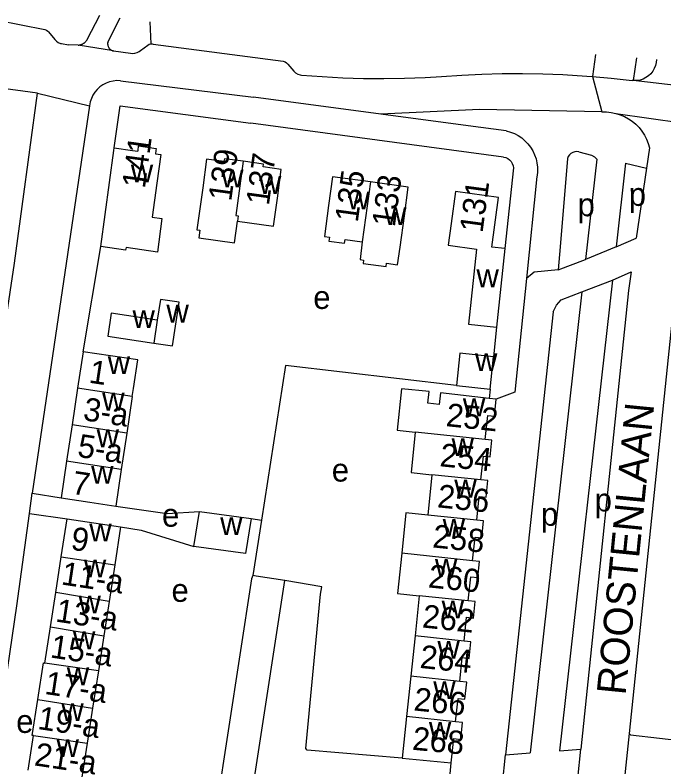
# Model space of a CAD drawing. Extents: x 161093 to 163177, y 379000 to 380904.
# Drawn here: x 162136.9 to 162248.8, y 380643.6 to 380773.4 of the extents above; entities that cross this region are included whole.
import ezdxf

# ---------------------------------------------------------------- set-up
doc = ezdxf.new("R2010")
doc.units = 0
for name, color, linetype in [('BLT_Basislijn', 7, 'Continuous'), ('BLT_Bebouwing', 7, 'Continuous'), ('BLT_Centroide', 7, 'Continuous'), ('BLT_Huisnummer', 7, 'Continuous'), ('BLT_Huisnummer_ tussenligend', 7, 'Continuous'), ('BLT_Huisnummer_reeks', 7, 'Continuous'), ('BLT_Onderverdeling_panden', 7, 'Continuous'), ('BLT_Straatnaam', 7, 'Continuous'), ('BLT_Vlakafsluiter', 7, 'Continuous')]:
    doc.layers.add(name, color=color, linetype=linetype)

msp = doc.modelspace()

# ---------------------------------------------------------------- linework, layer by layer
at = {"layer": 'BLT_Basislijn'}
for p, q in [((162130.53, 380773.08), (162142.01, 380770.9)), ((162149.32, 380769.16), (162151.51, 380773.37)), ((162152.85, 380768.67), (162154.99, 380772.89)), ((162160.13, 380772.18), (162160.28, 380768.4)), ((162142.62, 380770.47), (162143.7, 380769.17)), ((162144.85, 380768.43), (162146.08, 380768.25)), ((162147.74, 380768.18), (162146.08, 380768.25)), ((162153.82, 380767.17), (162147.74, 380768.18)), ((162158.49, 380767.27), (162159.79, 380768.19)), ((162160.71, 380768.33), (162183.14, 380765.38)), ((162153.82, 380767.17), (162156.78, 380766.8)), ((162237, 380766.53), (162236.48, 380762.74)), ((162244.12, 380765.98), (162243.54, 380762.07)), ((162247.55, 380765.72), (162247.48, 380765.16)), ((162183.92, 380764.89), (162184.95, 380763.68)), ((162155.04, 380762.03), (162178.01, 380759.21)), ((162243.54, 380762.07), (162243.36, 380762.08)), ((162200, 380756.26), (162178.01, 380759.21)), ((162149.68, 380757.7), (162139.81, 380690.86)), ((162215.06, 380754.25), (162200, 380756.26)), ((162221.13, 380748.86), (162177.52, 380754.69)), ((162221.62, 380753.37), (162215.06, 380754.25)), ((162232.19, 380748.6), (162230.93, 380733.36)), ((162222.85, 380747), (162221.35, 380733.05)), ((162242.19, 380747.81), (162245.81, 380746.93)), ((162148.61, 380715.26), (162151.65, 380733.4)), ((162230.93, 380733.36), (162230.6, 380729.38)), ((162240.57, 380733.34), (162235.29, 380731.15)), ((162234.66, 380725.57), (162239.93, 380727.62)), ((162229.74, 380722.16), (162221.47, 380645.69)), ((162219.91, 380719.49), (162219.43, 380714.38)), ((162218.85, 380708.82), (162218.7, 380707.18)), ((162139.32, 380687.33), (162139.81, 380690.86)), ((162139.81, 380690.86), (162144.79, 380690.03)), ((162139.32, 380687.33), (162145.83, 380686.43)), ((162177.6, 380686.44), (162179.36, 380686.16)), ((162179.36, 380686.16), (162177.86, 380676.61)), ((162220.95, 380640.64), (162221.47, 380645.69)), ((162221.47, 380645.69), (162225.75, 380646)), ((162230.82, 380646.36), (162234.52, 380646.63)), ((162233.98, 380641.58), (162234.52, 380646.63)), ((162211.69, 380639.44), (162212.13, 380644.29))]:
    msp.add_line(p, q, dxfattribs=at)
for points in [[(162140.7, 380759.86), (162051.87, 380771.94)], [(162142.01, 380770.9), (162142.29, 380770.78), (162142.52, 380770.6), (162142.62, 380770.47)], [(162143.7, 380769.17), (162143.98, 380768.87), (162144.32, 380768.64), (162144.69, 380768.48), (162144.85, 380768.43)], [(162147.74, 380768.18), (162147.82, 380768.18), (162147.91, 380768.19), (162147.99, 380768.21), (162148.07, 380768.22), (162148.15, 380768.25), (162148.23, 380768.27), (162148.31, 380768.3), (162148.39, 380768.33), (162148.47, 380768.37), (162148.54, 380768.41), (162148.62, 380768.45), (162148.69, 380768.49), (162148.76, 380768.54), (162148.83, 380768.59), (162148.89, 380768.65), (162148.96, 380768.71), (162149.02, 380768.77), (162149.08, 380768.83), (162149.13, 380768.89), (162149.18, 380768.96), (162149.23, 380769.02), (162149.27, 380769.09), (162149.32, 380769.16)], [(162152.85, 380768.67), (162152.84, 380768.59), (162152.83, 380768.51), (162152.83, 380768.43), (162152.83, 380768.35), (162152.84, 380768.26), (162152.85, 380768.18), (162152.87, 380768.1), (162152.9, 380768.01), (162152.93, 380767.93), (162152.97, 380767.85), (162153.01, 380767.77), (162153.06, 380767.69), (162153.12, 380767.62), (162153.17, 380767.55), (162153.24, 380767.49), (162153.3, 380767.43), (162153.37, 380767.38), (162153.44, 380767.33), (162153.52, 380767.29), (162153.59, 380767.25), (162153.67, 380767.22), (162153.74, 380767.19), (162153.82, 380767.17)], [(162159.79, 380768.19), (162160.02, 380768.33), (162160.28, 380768.4), (162160.54, 380768.38), (162160.71, 380768.33)], [(162156.78, 380766.8), (162157.16, 380766.75), (162157.55, 380766.78), (162157.92, 380766.89), (162158.26, 380767.08), (162158.49, 380767.27)], [(162183.14, 380765.38), (162183.44, 380765.28), (162183.71, 380765.11), (162183.92, 380764.89)], [(162247.48, 380765.16), (162247.36, 380764.64), (162247.16, 380764.13), (162246.89, 380763.66), (162246.55, 380763.24), (162246.15, 380762.87), (162245.71, 380762.56), (162245.22, 380762.32), (162244.71, 380762.15), (162244.17, 380762.07), (162243.54, 380762.07)], [(162184.95, 380763.68), (162185.27, 380763.4), (162185.65, 380763.19), (162186.05, 380763.06), (162186.31, 380763.01)], [(162186.31, 380763.01), (162189.85, 380762.74), (162193.4, 380762.55), (162196.96, 380762.43), (162200.51, 380762.4), (162204.07, 380762.45), (162207.62, 380762.58), (162210.45, 380762.74)], [(162210.45, 380762.74), (162213.93, 380763), (162217.42, 380763.18), (162220.92, 380763.28), (162224.41, 380763.3), (162227.91, 380763.24), (162231.37, 380763.11)], [(162231.37, 380763.11), (162235.55, 380762.83), (162236.48, 380762.74)], [(162236.48, 380762.74), (162239.72, 380762.46), (162243.36, 380762.08)], [(162155.04, 380762.03), (162154.41, 380762.05), (162153.78, 380761.98), (162153.17, 380761.84), (162152.58, 380761.62), (162152.02, 380761.32), (162151.51, 380760.96), (162151.04, 380760.54), (162150.63, 380760.06), (162150.29, 380759.53), (162150.02, 380758.97), (162149.82, 380758.37), (162149.68, 380757.7)], [(162130.89, 380691.66), (162130.95, 380692.04), (162136.73, 380730.54), (162140.7, 380759.86)], [(162153.97, 380750.43), (162154.99, 380757.7), (162177.52, 380754.69)], [(162238.14, 380756.64), (162217.02, 380757.08), (162200, 380756.26)], [(162238.14, 380756.64), (162238.93, 380756.64), (162239.73, 380756.56), (162240.52, 380756.4)], [(162240.52, 380756.4), (162241.28, 380756.17), (162242.01, 380755.86), (162242.71, 380755.48), (162243.37, 380755.03), (162243.99, 380754.52), (162244.54, 380753.95), (162245.04, 380753.32), (162245.47, 380752.65), (162245.83, 380751.94), (162246.12, 380751.2), (162246.33, 380750.46)], [(162221.62, 380753.37), (162222.33, 380753.18), (162223.02, 380752.91), (162223.67, 380752.56), (162224.29, 380752.15), (162224.85, 380751.68), (162225.37, 380751.14), (162225.82, 380750.56), (162226.2, 380749.93), (162226.52, 380749.26), (162226.76, 380748.56), (162226.92, 380747.84), (162227.01, 380747.1), (162227.01, 380746.36), (162226.94, 380745.63), (162226.92, 380745.5)], [(162234.16, 380749.74), (162233.81, 380749.79), (162233.45, 380749.76), (162233.1, 380749.66), (162232.79, 380749.48), (162232.53, 380749.23), (162232.32, 380748.93), (162232.19, 380748.6)], [(162234.16, 380749.74), (162236.36, 380749.21), (162236.83, 380748.92), (162237.24, 380748.52)], [(162246.33, 380750.46), (162245.81, 380746.93)], [(162221.13, 380748.86), (162221.52, 380748.77), (162221.88, 380748.6), (162222.2, 380748.37), (162222.46, 380748.08), (162222.67, 380747.74), (162222.8, 380747.36), (162222.85, 380747)], [(162237.24, 380748.52), (162235.29, 380731.15)], [(162242.19, 380747.81), (162240.57, 380733.34)], [(162245.81, 380746.93), (162244.04, 380734.83)], [(162226.92, 380745.5), (162225.11, 380727.92)], [(162240.57, 380733.34), (162244.04, 380734.83)], [(162230.6, 380729.38), (162235.29, 380731.15)], [(162230.6, 380729.38), (162226.41, 380728.96), (162225.11, 380727.92)], [(162243.18, 380729.02), (162242.71, 380725.8), (162234.52, 380646.63)], [(162239.93, 380727.62), (162243.18, 380729.02)], [(162225.11, 380727.92), (162223.09, 380708.29), (162219.9, 380707.04)], [(162239.93, 380727.62), (162230.82, 380646.36)], [(162250.94, 380726.78), (162250.65, 380724.81), (162242.85, 380649.38)], [(162234.66, 380725.57), (162225.75, 380646)], [(162229.74, 380722.16), (162230.31, 380723.28), (162231.08, 380724.22), (162234.66, 380725.57)], [(162213.03, 380709.43), (162183.53, 380712.88), (162179.36, 380686.16)], [(162154.22, 380688.6), (162163.08, 380687.33), (162168.67, 380687.67)], [(162128.74, 380587.12), (162128.39, 380587.13), (162125.11, 380587.63), (162124.98, 380588.22), (162137.14, 380671.41), (162139.32, 380687.33)], [(162155.07, 380685.01), (162158.61, 380684.46), (162167.7, 380681.66)], [(162203.66, 380645.09), (162187.26, 380646.49), (162187.04, 380646.75), (162189.54, 380673.4), (162189.78, 380674.67), (162183.39, 380675.76)], [(162242.85, 380649.38), (162243.05, 380649.1), (162253.09, 380647.99)]]:
    msp.add_lwpolyline(points, dxfattribs=at)
at = {"layer": 'BLT_Bebouwing'}
for p, q in [((162221.37, 380733.05), (162220.66, 380726.56)), ((162221.37, 380733.05), (162221.35, 380733.05)), ((162220.66, 380726.56), (162219.91, 380719.49)), ((162148.61, 380715.26), (162147.65, 380708.95)), ((162218.85, 380708.82), (162219.43, 380714.38)), ((162213.03, 380709.43), (162218.85, 380708.82)), ((162147.65, 380708.95), (162146.7, 380702.65)), ((162157.08, 380707.53), (162156.13, 380701.22)), ((162146.7, 380702.65), (162145.75, 380696.34)), ((162156.13, 380701.22), (162155.17, 380694.91)), ((162145.75, 380696.34), (162144.79, 380690.03)), ((162155.17, 380694.91), (162154.22, 380688.6)), ((162208.8, 380694.03), (162208.07, 380687.06)), ((162167.7, 380681.66), (162168.67, 380687.67)), ((162168.67, 380687.67), (162177.6, 380686.44)), ((162143.88, 380673.71), (162144.83, 380679.86)), ((162154.06, 380678.46), (162153.08, 380672.13)), ((162177.86, 380676.61), (162177.68, 380676.03)), ((162142.97, 380667.76), (162143.88, 380673.71)), ((162206.61, 380673.14), (162205.88, 380666.2)), ((162153.08, 380672.13), (162152.16, 380666.22)), ((162142.01, 380661.52), (162142.97, 380667.76)), ((162152.16, 380666.22), (162151.23, 380660.18)), ((162205.88, 380666.2), (162205.15, 380659.24)), ((162151.23, 380660.18), (162150.23, 380653.73)), ((162205.15, 380659.24), (162204.42, 380652.28)), ((162150.23, 380653.73), (162149.3, 380647.7)), ((162204.42, 380652.28), (162203.66, 380645.09)), ((162139.11, 380643.03), (162140.03, 380648.99)), ((162149.3, 380647.7), (162148.39, 380641.81)), ((162203.66, 380645.09), (162212.13, 380644.29))]:
    msp.add_line(p, q, dxfattribs=at)
for points in [[(162153.97, 380750.43), (162157.11, 380750), (162158.06, 380749.87), (162158.08, 380750), (162158.18, 380750.77), (162161.22, 380750.36), (162161.17, 380750), (162161.1, 380749.43), (162162.02, 380749.3), (162161.34, 380744.35), (162160.54, 380738.47), (162162.21, 380738.24), (162161.41, 380732.43), (162156, 380733.24), (162155.94, 380732.81), (162151.65, 380733.4)], [(162151.65, 380733.4), (162153.91, 380750), (162153.97, 380750.43)], [(162176.23, 380748.12), (162172.97, 380748.57), (162172.9, 380748.1), (162169.92, 380748.51), (162169.24, 380743.57), (162168.25, 380736.29), (162168.75, 380736.22), (162168.57, 380734.89), (162174.71, 380734.06), (162175.22, 380737.77)], [(162175.22, 380737.77), (162181.46, 380736.91), (162182.13, 380741.77), (162182.8, 380746.73), (162179.65, 380747.16), (162179.72, 380747.65), (162176.23, 380748.12)], [(162198.17, 380744.57), (162191.64, 380745.46), (162190.96, 380740.51), (162190.23, 380735.13), (162191.11, 380735.01), (162191.02, 380734.36), (162193.73, 380733.99), (162193.82, 380734.6), (162196.76, 380734.2)], [(162196.76, 380734.2), (162196.39, 380731.15), (162196.99, 380731.06), (162196.91, 380730.5), (162200.9, 380729.95), (162200.98, 380730.52), (162202.88, 380730.26), (162203.3, 380733.3), (162204.04, 380738.72), (162204.71, 380743.68), (162198.17, 380744.57)], [(162221.35, 380733.05), (162219.13, 380733.29), (162220.29, 380741.89), (162212.86, 380742.9), (162212.12, 380737.4), (162211.61, 380733.64), (162216.5, 380732.98), (162215.09, 380720.01), (162219.91, 380719.49)], [(162160.8, 380716.76), (162164.04, 380716.27), (162165.18, 380723.8), (162161.94, 380724.29), (162161.39, 380720.71)], [(162153.45, 380721.91), (162152.85, 380717.96), (162160.8, 380716.76)], [(162161.39, 380720.71), (162153.45, 380721.91)], [(162157.08, 380707.53), (162157.29, 380708.89), (162158.04, 380713.84), (162148.61, 380715.26)], [(162219.43, 380714.38), (162213.61, 380714.99), (162213.03, 380709.43)], [(162218.7, 380707.18), (162210.28, 380708.16), (162210.07, 380706.17), (162208.08, 380706.38), (162208.29, 380708.37), (162203.52, 380708.87), (162202.77, 380701.69), (162205.92, 380701.36)], [(162217.99, 380700.09), (162218.43, 380704.24), (162219.59, 380704.12), (162219.9, 380707.04)], [(162219.9, 380707.04), (162218.7, 380707.18)], [(162205.92, 380701.36), (162205.19, 380694.41), (162208.8, 380694.03)], [(162217.26, 380693.14), (162217.69, 380697.21), (162218.86, 380697.09), (162219.16, 380699.97), (162217.99, 380700.09)], [(162216.53, 380686.17), (162216.96, 380690.27), (162218.14, 380690.15), (162218.44, 380693.02), (162217.26, 380693.14)], [(162144.79, 380690.03), (162149.74, 380689.28), (162154.22, 380688.6)], [(162208.07, 380687.06), (162204.31, 380687.46), (162203.58, 380680.47)], [(162144.83, 380679.86), (162145.83, 380686.43)], [(162145.83, 380686.43), (162155.07, 380685.01)], [(162177.6, 380686.44), (162176.64, 380680.41), (162167.7, 380681.66)], [(162215.8, 380679.19), (162216.23, 380683.27), (162217.41, 380683.15), (162217.71, 380686.05), (162216.53, 380686.17)], [(162155.07, 380685.01), (162154.06, 380678.46)], [(162203.58, 380680.47), (162202.85, 380673.53), (162206.61, 380673.14)], [(162215.07, 380672.25), (162215.51, 380676.41), (162216.69, 380676.28), (162216.98, 380679.06), (162215.8, 380679.19)], [(162177.68, 380676.03), (162163.58, 380584.24), (162157.39, 380585.19)], [(162162.99, 380575.6), (162163.6, 380579.55), (162168.49, 380578.8), (162183.39, 380675.76)], [(162183.39, 380675.76), (162178.45, 380676.52), (162177.86, 380676.61)], [(162214.34, 380665.31), (162214.77, 380669.41), (162215.96, 380669.29), (162216.26, 380672.12), (162215.07, 380672.25)], [(162213.61, 380658.35), (162214.04, 380662.45), (162215.23, 380662.32), (162215.53, 380665.18), (162214.34, 380665.31)], [(162140.78, 380655.2), (162141.76, 380661.56), (162142.01, 380661.52)], [(162212.88, 380651.39), (162213.3, 380655.41), (162214.5, 380655.29), (162214.81, 380658.23), (162213.61, 380658.35)], [(162140.03, 380648.99), (162139.83, 380649.02), (162140.78, 380655.2)], [(162212.13, 380644.29), (162212.57, 380648.48), (162213.78, 380648.35), (162214.08, 380651.26), (162212.88, 380651.39)]]:
    msp.add_lwpolyline(points, dxfattribs=at)
at = {"layer": 'BLT_Onderverdeling_panden'}
for p, q in [((162198.17, 380744.57), (162196.76, 380734.2)), ((162161.39, 380720.71), (162160.8, 380716.76)), ((162157.08, 380707.53), (162147.65, 380708.95)), ((162156.13, 380701.22), (162146.7, 380702.65)), ((162217.99, 380700.09), (162205.92, 380701.36)), ((162155.17, 380694.91), (162145.75, 380696.34)), ((162217.26, 380693.14), (162208.8, 380694.03)), ((162216.53, 380686.17), (162208.07, 380687.06)), ((162144.83, 380679.86), (162154.06, 380678.46)), ((162215.8, 380679.19), (162203.58, 380680.47)), ((162153.08, 380672.13), (162143.88, 380673.71)), ((162215.07, 380672.25), (162206.61, 380673.14)), ((162142.97, 380667.76), (162152.16, 380666.22)), ((162214.34, 380665.31), (162205.88, 380666.2)), ((162151.23, 380660.18), (162142.01, 380661.52)), ((162213.61, 380658.35), (162205.15, 380659.24)), ((162140.78, 380655.2), (162150.23, 380653.73)), ((162212.88, 380651.39), (162204.42, 380652.28)), ((162140.03, 380648.99), (162149.3, 380647.7))]:
    msp.add_line(p, q, dxfattribs=at)
msp.add_lwpolyline([(162176.23, 380748.12), (162174.96, 380738.76), (162175.35, 380738.71), (162175.22, 380737.77)], dxfattribs=at)
at = {"layer": 'BLT_Vlakafsluiter'}
for p, q in [((162236.48, 380762.74), (162238.14, 380756.64)), ((162260.65, 380760.08), (162243.54, 380762.07)), ((162140.7, 380759.86), (162149.68, 380757.7)), ((162240.52, 380756.4), (162262.39, 380753.23))]:
    msp.add_line(p, q, dxfattribs=at)
msp.add_lwpolyline([(162242.85, 380649.38), (162242.28, 380643.87), (162241.6, 380637.62)], dxfattribs=at)

# ---------------------------------------------------------------- texts
at = {"layer": 'BLT_Centroide'}
for s, p in [('w', (162156.83, 380744.5)), ('w', (162172.42, 380743.62)), ('w', (162178.94, 380742.5)), ('w', (162194.2, 380739.81)), ('p', (162242.76, 380740.43)), ('p', (162233.93, 380738.64)), ('w', (162200.55, 380737.12)), ('w', (162216.48, 380726.38)), ('e', (162188.32, 380722.64)), ('w', (162157.12, 380719.34)), ('w', (162162.98, 380720.28)), ('w', (162152.85, 380711.41)), ('w', (162216.23, 380711.91)), ('w', (162151.89, 380705.09)), ('w', (162214.14, 380704.12)), ('w', (162150.93, 380698.78)), ('w', (162212.18, 380697.25)), ('w', (162149.98, 380692.47)), ('e', (162191.51, 380692.84)), ('w', (162212.66, 380690.09)), ('p', (162236.88, 380687.68)), ('e', (162162.22, 380685.05)), ('p', (162227.61, 380685.21)), ('w', (162172.25, 380683.6)), ('w', (162210.65, 380683.31)), ('w', (162149.67, 380682.5)), ('w', (162148.73, 380676.31)), ('w', (162209.32, 380676.38)), ('e', (162163.85, 380672.08)), ('w', (162147.8, 380670.09)), ('w', (162210.47, 380669.22)), ('w', (162146.85, 380663.91)), ('w', (162209.74, 380662.28)), ('w', (162145.78, 380657.69)), ('w', (162209.02, 380655.31)), ('w', (162144.84, 380651.5)), ('e', (162137.05, 380649.46)), ('w', (162208.27, 380648.28)), ('w', (162144.01, 380645.28))]:
    msp.add_text(s, height=4, dxfattribs=at).set_placement(p)
at = {"layer": 'BLT_Huisnummer'}
for s, rotation, p in [('141', 82.2297, (162159.25, 380743.33)), ('139', 82.2392, (162174.15, 380741.12)), ('137', 82.2301, (162180.65, 380740.39)), ('135', 82.2353, (162195.99, 380737.47)), ('133', 82.333, (162202.38, 380736.67)), ('131', 82.3303, (162217.52, 380735.68)), ('1', 351.3982, (162149.46, 380709.93)), ('252', 354.004, (162211.11, 380702.42)), ('7', 351.3967, (162146.51, 380690.75)), ('256', 354.004, (162209.62, 380688.41)), ('9', 351.3972, (162146.33, 380681.12)), ('260', 354.004, (162208.04, 380674.59)), ('264', 354.004, (162206.6, 380660.69)), ('268', 354.6526, (162205.3, 380646.56))]:
    msp.add_text(s, height=4, rotation=rotation, dxfattribs=at).set_placement(p)
at = {"layer": 'BLT_Huisnummer_ tussenligend'}
for s, p in [('254', (162210.04, 380695.5)), ('258', (162208.79, 380681.49)), ('262', (162207.01, 380667.67)), ('266', (162205.55, 380653.35))]:
    msp.add_text(s, height=4, rotation=354.004, dxfattribs=at).set_placement(p)
at = {"layer": 'BLT_Huisnummer_reeks'}
for s, rotation, p in [('3-a', 351.3982, (162148.46, 380703.46)), ('5-a', 351.3982, (162147.48, 380697.14)), ('11-a', 351.3972, (162144.68, 380675.1)), ('13-a', 351.3962, (162143.71, 380668.7)), ('15-a', 351.3962, (162142.78, 380662.5)), ('17-a', 351.3938, (162141.83, 380656.2)), ('19-a', 351.3938, (162140.62, 380650.15)), ('21-a', 351.394, (162140.04, 380643.87))]:
    msp.add_text(s, height=4, rotation=rotation, dxfattribs=at).set_placement(p)
at = {"layer": 'BLT_Straatnaam'}
msp.add_text('ROOSTENLAAN', height=5, rotation=84.3671, dxfattribs=at).set_placement((162242.2, 380655.88))

doc.saveas('drawing.dxf')
